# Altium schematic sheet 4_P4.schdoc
size 307 x 218 mm; Symbol: Sheet-Symbol_A4; Device: Sheet-Symbol_A4; @Project Name: Project Name; @Page Count: 3; @Update Date: 2021.11.05; @Create Date: 2024-11-24; @Schematic Name: Schematic Name; @Page No: 1; @Page Name: P1; Company: EasyEDA.com; Version: V1.0; Page Size: A4; @Create Time: 4:06:41 PM; @Update Time: 1:48:47 AM; Title Block Position: 3; Width: 1170; Height: 825; Region Start: 1; X Region Count: 6; Y Region Count: 4; Blade Width: 10; @Board Name: PENTASLAM
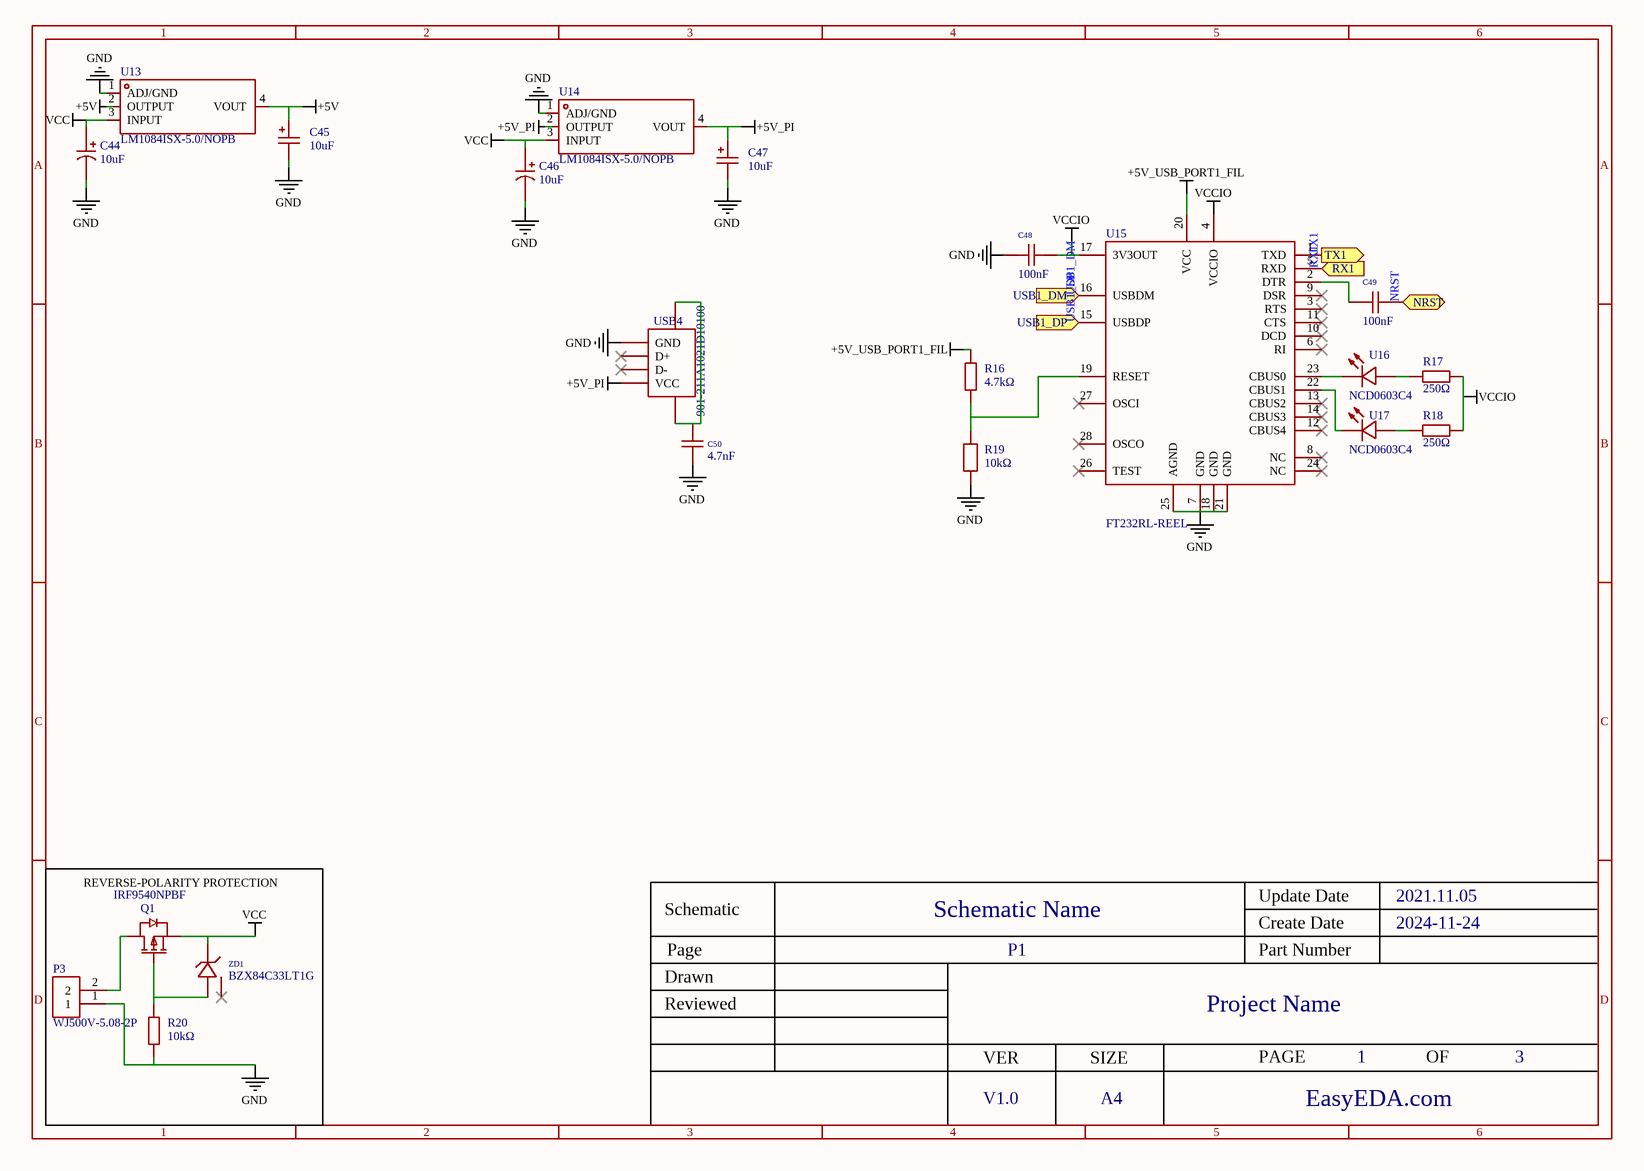
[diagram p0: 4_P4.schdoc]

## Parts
C44  10uF  [CAP-SMD_BD4.0-L4.3-W4.3-FD]
C45  10uF  [CAP-SMD_L3.2-W1.6-RD-C7171]
C46  10uF  [CAP-SMD_BD4.0-L4.3-W4.3-FD]
C47  10uF  [CAP-SMD_L3.2-W1.6-RD-C7171]
C48  100nF  [C0402]
C49  100nF  [C0603]
C50  4.7nF  [C0402]
P3  WJ500V-5.08-2P  [CONN-TH_2P-P5.00_WJ500V-5.08-2P]
Q1  IRF9540NPBF  [TO-220-3_L10.0-W4.5-P2.54-L]
R16  4.7kΩ  [R0603]
R17  250Ω  [R0603]
R18  250Ω  [R0603]
R19  10kΩ  [R0603]
R20  10kΩ  [R0402]
U13  LM1084ISX-5.0/NOPB  [TO-263-3_L10.2-W8.6-P2.54-LS14.4-TL]
U14  LM1084ISX-5.0/NOPB  [TO-263-3_L10.2-W8.6-P2.54-LS14.4-TL]
U15  FT232RL-REEL  [SSOP-28_L10.2-W5.3-P0.65-LS7.8-BL]
U16  NCD0603C4  [LED0603-RD]
U17  NCD0603C4  [LED0603-RD]
USB4  901-211A1021D10100  [USB-A-TH_USB-M-1_C2346]
ZD1  BZX84C33LT1G  [SOT-23-3_L2.9-W1.6-P1.90-LS2.8-BR]

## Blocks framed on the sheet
REVERSE-POLARITY PROTECTION: P3 Q1 R20 ZD1

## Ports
NRST (bidir), RX1 (in), TX1 (out), USB1_DM (in), USB1_DP (in)

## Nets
+5V: C45.1 U13.2(OUTPUT) U13.4(VOUT)
+5V_PI: C47.1 U14.2(OUTPUT) U14.4(VOUT) USB4.1(VCC)
+5V_USB_PORT1_FIL: R16.2 U15.20(VCC)
GND: C44.2 C45.2 C46.2 C47.2 C48.1 C50.1 P3.1 R19.2 R20.1 U13.1(ADJ/GND) U14.1(ADJ/GND) U15.7(GND) U15.18(GND) U15.21(GND) U15.25(AGND) USB4.4(GND)
VCC: C44.1 C46.1 Q1.3(S) U13.3(INPUT) U14.3(INPUT) ZD1.3(K)
VCCIO: C48.2 R17.2 R18.2 U15.4(VCCIO) U15.17(3V3OUT)
NRST: C49.2 ; port NRST
RX1: U15.5(RXD) ; port RX1
TX1: U15.1(TXD) ; port TX1
USB1_DM: U15.16(USBDM) ; port USB1_DM
USB1_DP: U15.15(USBDP) ; port USB1_DP
NetC49_1: C49.1 U15.2(DTR)
NetC50_2: C50.2 USB4.0
NetP3_2: P3.2 Q1.2(D)
NetQ1_1: Q1.1(G) R20.2 ZD1.1(A)
NetR16_1: R16.1 R19.1 U15.19(RESET)
NetR17_1: R17.1 U16.2(+)
NetR18_1: R18.1 U17.2(+)
NetU15_22: U15.22(CBUS1) U17.1(-)
NetU15_23: U15.23(CBUS0) U16.1(-)

Not connected (* = marked no-connect by the designer): U15 3(RTS)* 6(RI)* 8(NC)* 9(DSR)* 10(DCD)* 11(CTS)* 12(CBUS4)* 13(CBUS2)* 14(CBUS3)* 24(NC)* 26(TEST)* 27(OSCI)* 28(OSCO)*; USB4 2(D-)* 3(D+)*; ZD1 2(nc)*

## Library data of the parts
C44 C46 = RST10UF16V013: Manufacturer: KNSCHA(科尼盛); Add into BOM: yes; Tolerance: ±20%; Ripple Current: 14mA@120Hz; Lifetime @ Temp: 2000hrs@105℃
C45 C47 = TAJA106K016RNJ: Manufacturer: Kyocera AVX; Add into BOM: yes; Tolerance: ±10%; Equivalent Series Resistance(ESR): 3Ω@100kHz
C48 = CC0402KRX7R7BB104: Manufacturer: YAGEO(国巨); Add into BOM: yes; Tolerance: ±10%
C49 = CC0603KRX7R9BB104: Manufacturer: YAGEO(国巨); Add into BOM: yes; Tolerance: ±10%
C50 = CC0402KRX7R9BB472: Manufacturer: YAGEO(国巨); Add into BOM: yes; Tolerance: ±10%
P3 = WJ500V-5.08-2P: Manufacturer: KANGNEX(康奈克斯电气); Symbol: WJ500V-5.08-2P-14-00A; Add into BOM: yes; Structure: 1x2P; Pitch: 5.08mm; Current Rating (Max): 18A; Voltage Rating (Max): 250V; Wire Gauge - AWG: 14~30; Wire Gauge - mm2: 2.5; Number of PINs Per Row: 2; Screw Specification: M2.5
Q1 = IRF9540NPBF: Manufacturer: Infineon(英飞凌); Add into BOM: yes; Type: 1个PChannel; Drain Source On Resistance (RDS(on)@Vgs,Id): 117mΩ@10V,11A; Gate Threshold Voltage (Vgs(th)@Id): 4V@250uA; Total Gate Charge (Qg@Vgs): 97nC@10V; Input Capacitance (Ciss@Vds): 1.3nF@25V
R16 = RC0603JR-074K7L: Manufacturer: YAGEO(国巨); Add into BOM: yes; Tolerance: ±5%; Temperature Coefficient: ±100ppm/℃
R17 R18 = RT0603BRE07250RL: Manufacturer: YAGEO(国巨); Add into BOM: yes; Tolerance: ±0.1%; Temperature Coefficient: ±50ppm/℃
R19 = FRC0603J103TS: Manufacturer: FOJAN(富捷); Add into BOM: yes; Tolerance: ±5%; Temperature Coefficient: ±100ppm/℃
R20 = RC0402FR-0710KL: Manufacturer: YAGEO(国巨); Add into BOM: yes; Tolerance: ±1%; Temperature Coefficient: ±100ppm/℃
U13 U14 = LM1084ISX-5.0/NOPB: Manufacturer: TI(德州仪器); Add into BOM: yes; Output Type: Fixed; Maximum Input Voltage: 25V; Output Voltage: 5V; Output Current: 5A; Power Supply Rejection Ratio (PSRR): 68dB@(120Hz); Dropout Voltage: 1.5V@(5A); standby current: 10mA; Output Polarity: Positive electrode; Number of Outputs: 1
U15 = FT232RL-REEL: Manufacturer: FTDI(飞特帝亚); Add into BOM: yes; Applications Function: USB转UART; Protocol: UART; Supply Voltage: 3.3V~5.25V
U16 U17 = NCD0603C4: Manufacturer: 国星光电; Add into BOM: yes; Emitted Color: Green-yellow; Forward Voltage (VF): 1.6V~2.6V; Power Dissipation: 65mW; Forward Current: 25mA; Dominant Wavelength: 565nm~578nm; Peak Wavelength: 576nm; Lens Color: 无色透明透镜; Luminous Intensity: 5mcd~13mcd; Viewing Angle: 140°
USB4 = 901-211A1021D10100: Manufacturer: 精拓金; Symbol: USB A/F 90° Outside the buckle straight foot; Add into BOM: yes; Connector Type: Type-A; Gender: Female; Number of Ports: 1; Number of Contacts: 4P
ZD1 = BZX84C33LT1G: Manufacturer: onsemi(安森美); Add into BOM: yes; Diode Configuration: Single; Zener Voltage (Nom): 33V; Reverse Leakage Current (Ir): 50nA@23.1V; Zener Voltage (Range): 31V~35V; Power Dissipation: 225mW; Zener Impedance (Zzt): 80Ω; Tolerance: ±6%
